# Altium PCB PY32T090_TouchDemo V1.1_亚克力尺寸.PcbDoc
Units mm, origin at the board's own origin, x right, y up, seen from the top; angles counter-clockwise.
Board outline 86.5 x 140.97 mm, 2 copper layers (Top Layer, Bottom Layer); 4 components, 143 nets, 4 pads, 0 vias.
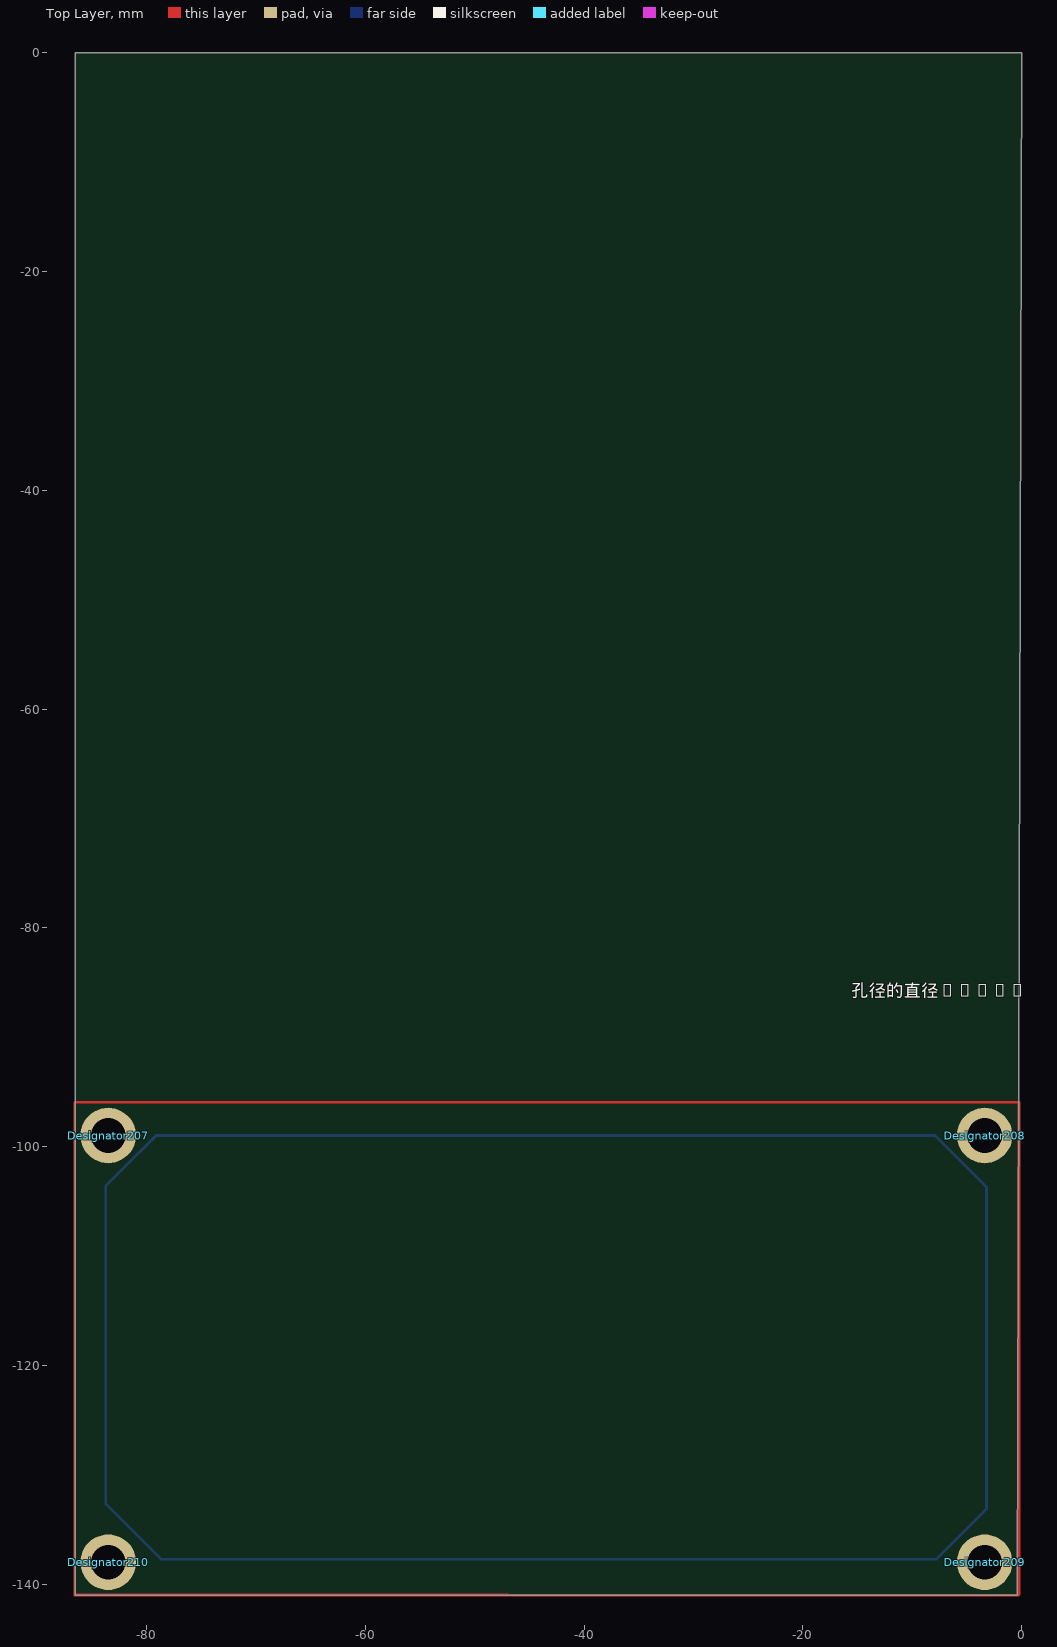
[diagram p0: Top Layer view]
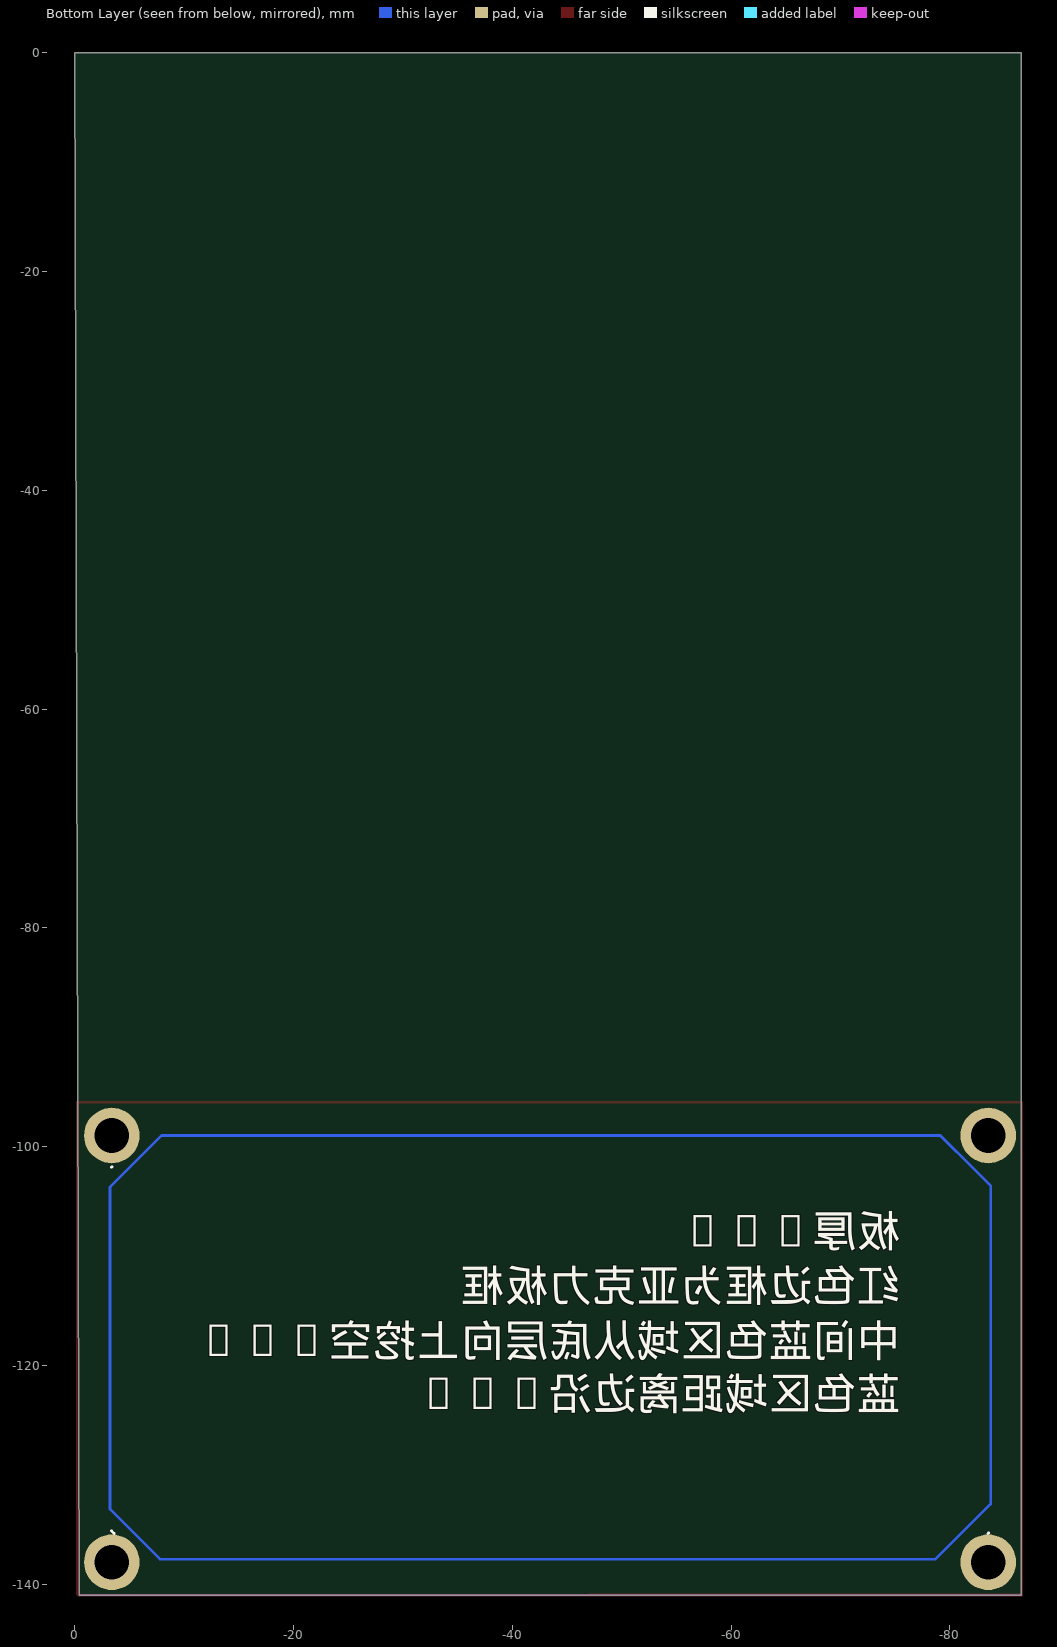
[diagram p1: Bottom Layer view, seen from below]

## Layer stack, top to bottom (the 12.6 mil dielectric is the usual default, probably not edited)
Top Solder: solder mask 0.0102, Solder Resist, Dk 3.5
Top Layer: signal copper 0.0356
Dielectric 1: dielectric 0.32, FR-4, Dk 4.8
Bottom Layer: signal copper 0.0356
Bottom Solder: solder mask 0.0102, Solder Resist, Dk 3.5

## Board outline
-86.5,-140.97 -86.5,0 0,0 -0.394,-140.97

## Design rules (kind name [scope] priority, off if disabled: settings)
Clearance Clearance_17 [All vs InNet('NetC3_2')] p1: gap=0.6 ignorepadtopadclearanceinfootprint=FALSE
Clearance Clearance_16 [All vs InNet('NetC8_2')] p2: gap=0.6 ignorepadtopadclearanceinfootprint=FALSE
Clearance Clearance_15 [All vs InNet('NetC11_2')] p3: gap=0.6 ignorepadtopadclearanceinfootprint=FALSE
Clearance Clearance_14 [All vs InNet('NetC13_2')] p4: gap=0.6 ignorepadtopadclearanceinfootprint=FALSE
Clearance Clearance_13 [All vs InNet('NetC24_2')] p5: gap=0.6 ignorepadtopadclearanceinfootprint=FALSE
Clearance Clearance_12 [All vs InNet('NetC22_2')] p6: gap=0.6 ignorepadtopadclearanceinfootprint=FALSE
Clearance Clearance_11 [All vs InNet('NetC19_2')] p7: gap=0.6 ignorepadtopadclearanceinfootprint=FALSE
Clearance Clearance_10 [All vs InNet('NetC15_2')] p8: gap=0.6 ignorepadtopadclearanceinfootprint=FALSE
Clearance Clearance_9 [All vs InNet('shield_pad')] p9: gap=1 ignorepadtopadclearanceinfootprint=FALSE
Clearance Clearance_18 [All vs InNet('NetC4_2')] p10: gap=1 ignorepadtopadclearanceinfootprint=FALSE
Clearance [All vs InNet('NetC5_2')] p11: gap=1 ignorepadtopadclearanceinfootprint=FALSE
Clearance Clearance_8 [All vs InNet('NetC17_2')] p12: gap=1 ignorepadtopadclearanceinfootprint=FALSE
Clearance Clearance_7 [All vs InNet('NetC14_2')] p13: gap=1 ignorepadtopadclearanceinfootprint=FALSE
Clearance Clearance_6 [All vs InNet('NetC9_2')] p14: gap=1 ignorepadtopadclearanceinfootprint=FALSE
Clearance Clearance_5 [All vs InNet('NetC12_2')] p15: gap=1 ignorepadtopadclearanceinfootprint=FALSE
Clearance Clearance_4 [All vs InNet('NetC21_2')] p16: gap=1 ignorepadtopadclearanceinfootprint=FALSE
Clearance Clearance_3 [All vs InNet('NetC16_2')] p17: gap=1 ignorepadtopadclearanceinfootprint=FALSE
Clearance Clearance_2 [All vs InNet('NetC23_2')] p18: gap=1 ignorepadtopadclearanceinfootprint=FALSE
Clearance Clearance_1 [All] p19: gap=0.2 ignorepadtopadclearanceinfootprint=FALSE
PlaneConnect [All] p1: planeconnectstyle=Direct reliefexpansion=0.508 reliefentries=4 reliefconductorwidth=0.254 reliefairgap=0.254
PolygonConnect [All] p1: connectstyle=Direct reliefconductorwidth=0.254 reliefentries=4 polygonreliefangle="90 Angle" airgapwidth=0.254
RoutingVias [All] p1: holewidth=0.711 width=1.27 viastyle="Through Hole" minholewidth=0.711 minwidth=1.27 maxholewidth=0.711 maxwidth=1.27
SolderMaskExpansion [All] p1: expansion=0.102 istentingtop=FALSE
Width [All] p1: maxlimit=1 minlimit=0.2 preferedwidth=0.254
29 further rules are at their usual default settings.

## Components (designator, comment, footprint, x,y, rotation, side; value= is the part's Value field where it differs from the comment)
Designator207 "Comment" "M3 125X200"#1 -78.5,-102.759 r0 top
Designator208 "Comment" "M3 125X200"#2 1.027,-103.318 r0 top
Designator209 "Comment" "M3 125X200"#3 1.129,-140.554 r0 top
Designator210 "Comment" "M3 125X200"#4 -78.78,-140.173 r0 top

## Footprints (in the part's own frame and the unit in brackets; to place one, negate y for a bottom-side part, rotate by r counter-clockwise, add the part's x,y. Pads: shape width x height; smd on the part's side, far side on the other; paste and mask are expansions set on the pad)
"M3 125X200"#1 [mm] "M3螺丝孔，孔125Mil，焊盘200Mil"
  round 5.08 hole 3.175: 1(-5,3.789)
"M3 125X200"#2 [mm] "M3螺丝孔，孔125Mil，焊盘200Mil"
  round 5.08 hole 3.175: 1(-4.421,4.348)
"M3 125X200"#3 [mm] "M3螺丝孔，孔125Mil，焊盘200Mil"
  round 5.08 hole 3.175: 1(-4.523,2.584)
"M3 125X200"#4 [mm] "M3螺丝孔，孔125Mil，焊盘200Mil"
  round 5.08 hole 3.175: 1(-4.72,2.203)

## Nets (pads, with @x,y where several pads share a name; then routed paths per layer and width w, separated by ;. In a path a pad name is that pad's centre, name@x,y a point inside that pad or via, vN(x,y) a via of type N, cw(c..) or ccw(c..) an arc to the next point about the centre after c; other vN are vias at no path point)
backlight: 
beep: 
BOOT0: 
CMOD: 
COM0: 
COM1: 
COM2: 
COM3: 
COM4: 
COM5: 
COM6: 
COM7: 
DAC1_OUT: 
DCOM0: 
DCOM1: 
DSEG0: 
DSEG1: 
DSEG2: 
DSEG3: 
GND: 
KEY1: 
LED1: 
LED_MOSI: 
NetBEEP1_2: 
NetBOOT_2: 
NetC2_2: 
NetC3_2: 
NetC4_2: 
NetC5_2: 
NetC8_2: 
NetC9_2: 
NetC11_2: 
NetC12_2: 
NetC13_2: 
NetC14_2: 
NetC15_2: 
NetC16_2: 
NetC17_2: 
NetC18_2: 
NetC19_2: 
NetC20_1: 
NetC21_2: 
NetC22_2: 
NetC23_2: 
NetC24_2: 
NetE3_1: 
NetJUMP_1: 
NetLD1_1: 
NetLD1_3: 
NetLD2_3: 
NetLD3_3: 
NetLD4_3: 
NetLD5_3: 
NetLD6_3: 
NetLD7_3: 
NetLD8_3: 
NetLD9_3: 
NetLD10_3: 
NetLD11_3: 
NetLD12_3: 
NetLD13_3: 
NetLD14_3: 
NetLD15_3: 
NetLD16_3: 
NetLD17_3: 
NetLD18_3: 
NetLD19_3: 
NetLD20_3: 
NetLD21_3: 
NetLD22_3: 
NetLD23_3: 
NetLD24_3: 
NetLD25_3: 
NetLD26_3: 
NetLD27_3: 
NetLD28_3: 
NetLD29_3: 
NetLD30_3: 
NetLD31_3: 
NetLD32_3: 
NetLD33_3: 
NetLED1_2: 
NetLED2_1: 
NetLED3_1: 
NetLED4_1: 
NetLED5_1: 
NetLED6_1: 
NetLED7_1: 
NetLED8_1: 
NetLED9_1: 
NetLED10_1: 
NetLED11_1: 
NetQ1_1: 
NetQ1_3: 
NetQ2_1: 
NetQ2_3: 
NetR1_2: 
NetR4_2: 
NetR42_1: 
NRST: 
NTC: 
OSC32I: 
OSC32O: 
POWER: 
SEG0: 
SEG1: 
SEG2: 
SEG3: 
SEG4: 
SEG5: 
SEG6: 
SEG7: 
SEG8: 
SEG9: 
SEG10: 
SEG11: 
SEG12: 
SEG13: 
Shield: 
shield_pad: 
Slider0: 
Slider1: 
Slider2: 
Slider3: 
SWC: 
SWD: 
TK0: 
TK1: 
TK2: 
TK3: 
TK4: 
TK5: 
TK6: 
TK7: 
USART1_RX: 
USART1_TX: 
V5V: 
VBUS: 
VCC: 
Wheel0: 
Wheel1: 
Wheel2: 
Wheel3: 
pads on no net: Designator207.1 Designator208.1 Designator209.1 Designator210.1
copper on no net: | length 495.3
  Top Layer w0.254: -86.563,-140.97 -46.99,-140.97 -46.965,-140.995 -0.33,-140.995 -0.254,-140.919 -0.254,-95.936 -86.512,-95.936 -86.563,-95.987 -86.563,-140.97
  Bottom Layer w0.254: -80.569,-100.432 -79.107,-98.97 -7.939,-98.97 -3.226,-103.683 -3.226,-133.121 -7.798,-137.693 -78.664,-137.693 -83.718,-132.639 -83.718,-103.556 -79.502,-99.339 ; -4.468,-101.049 -4.468,-100.811 -4.851,-100.427 -3.394,-98.97 ; -3.394,-137.97 -2.718,-137.294

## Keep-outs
Keep-Out Layer:
  lines w0.025: -86.5,-140.97 -0.394,-140.97

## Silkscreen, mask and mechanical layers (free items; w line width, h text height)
Top Overlay:
  text "孔径的直径3.2mm" at -15.594,-86.687 h2
Bottom Overlay:
  lines w0.254: -83.541,-135.28 -83.464,-135.357 ; -3.607,-135.357 -3.353,-135.103 ; -3.404,-101.829 -3.353,-101.879
  text "板厚5mm" at -75.484,-110.12 h5
  text "红色边框为亚克力板框" at -75.489,-115.098 h5
  text "中间蓝色区域从底层向上挖空3mm" at -75.489,-120.095 h5
  text "蓝色区域距离边沿3mm" at -75.484,-124.965 h5

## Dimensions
-3.394,-137.97 to -0.394,-137.97 on Top Overlay
-83.5,-137.97 to -86.5,-137.97 on Top Overlay
-3.394,-98.97 to -3.394,-95.97 on Top Overlay
-3.394,-98.97 to -0.394,-98.97 on Top Overlay
-83.5,-98.97 to -83.5,-95.97 on Top Overlay
-83.5,-98.97 to -86.5,-98.97 on Top Overlay
-3.394,-98.97 to -83.5,-98.97 on Top Overlay
-83.5,-137.97 to -86.512,-140.97 on Top Overlay
-3.394,-137.97 to -0.406,-140.97 on Top Overlay
-83.5,-98.97 to -83.5,-137.97 on Top Overlay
